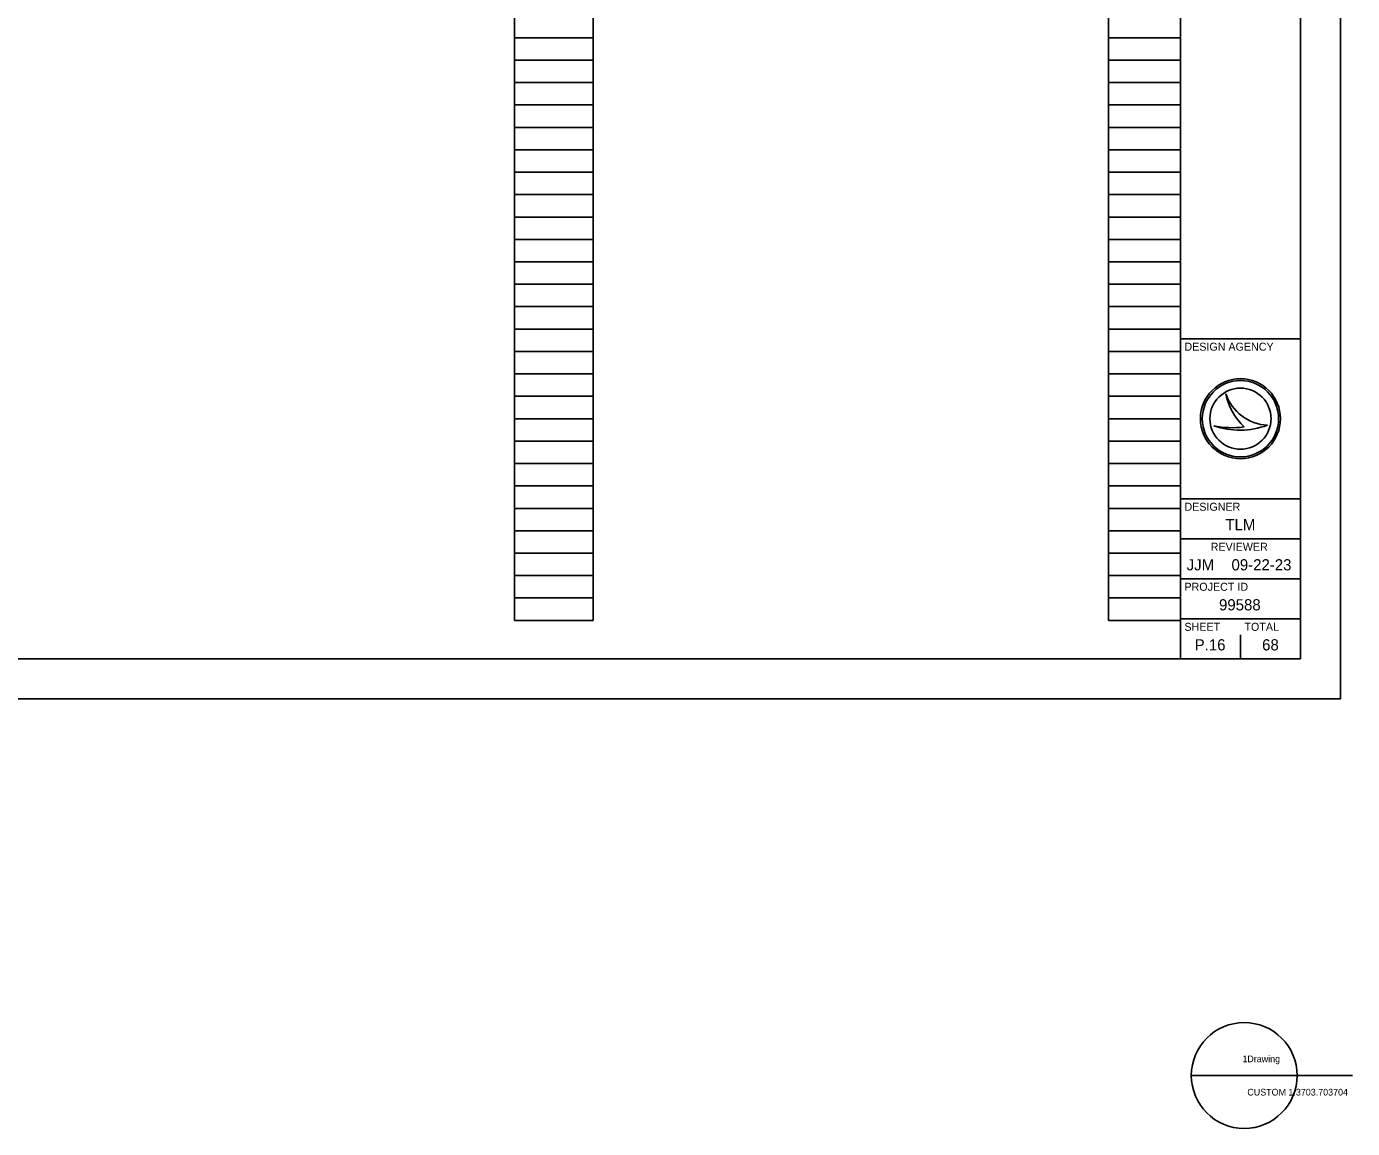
# Model space of a CAD drawing. Extents: x 0 to 34.1, y -5.4 to 22.
# Drawn here: x 17.58 to 34.15, y -5.37 to 8.4 of the extents above; entities that cross this region are included whole.
import ezdxf

# ---------------------------------------------------------------- set-up
doc = ezdxf.new("R2010")
doc.units = 0
for name, color, linetype in [('SH_Border', 7, 'Continuous'), ('SH_Cut_Line', 7, 'Continuous'), ('SH_Data', 7, 'Continuous'), ('SH_Text', 7, 'Continuous')]:
    doc.layers.add(name, color=color, linetype=linetype)

msp = doc.modelspace()

# ---------------------------------------------------------------- linework, layer by layer
at = {"layer": 'SH_Border'}
for p, q in [((32, 0.5), (32, 21.5)), ((32, 4.5), (33.5, 4.5)), ((32, 2.5), (33.5, 2.5)), ((32, 2), (33.5, 2)), ((32, 1.5), (33.5, 1.5)), ((32, 1), (33.5, 1))]:
    msp.add_line(p, q, dxfattribs=at)
msp.add_lwpolyline([(1.5, 21.5), (33.5, 21.5), (33.5, 0.5), (1.5, 0.5)], close=True, dxfattribs=at)
at = {"layer": 'SH_Cut_Line'}
msp.add_lwpolyline([(0, 0), (34, 0), (34, 22), (0, 22)], close=True, dxfattribs=at)
at = {"layer": 'SH_Data'}
for p, q in [((23.68, 0.98), (23.68, 21.14)), ((24.66, 0.98), (24.66, 21.14)), ((31.1, 0.98), (31.1, 21.14)), ((32, 0.98), (32, 21.14)), ((23.68, 8.26), (24.66, 8.26)), ((31.1, 8.26), (32, 8.26)), ((23.68, 7.98), (24.66, 7.98)), ((31.1, 7.98), (32, 7.98)), ((23.68, 7.7), (24.66, 7.7)), ((31.1, 7.7), (32, 7.7)), ((23.68, 7.42), (24.66, 7.42)), ((31.1, 7.42), (32, 7.42)), ((23.68, 7.14), (24.66, 7.14)), ((31.1, 7.14), (32, 7.14)), ((23.68, 6.86), (24.66, 6.86)), ((31.1, 6.86), (32, 6.86)), ((23.68, 6.58), (24.66, 6.58)), ((31.1, 6.58), (32, 6.58)), ((23.68, 6.3), (24.66, 6.3)), ((31.1, 6.3), (32, 6.3)), ((23.68, 6.02), (24.66, 6.02)), ((31.1, 6.02), (32, 6.02)), ((23.68, 5.74), (24.66, 5.74)), ((31.1, 5.74), (32, 5.74)), ((23.68, 5.46), (24.66, 5.46)), ((31.1, 5.46), (32, 5.46)), ((23.68, 5.18), (24.66, 5.18)), ((31.1, 5.18), (32, 5.18)), ((23.68, 4.9), (24.66, 4.9)), ((31.1, 4.9), (32, 4.9)), ((23.68, 4.62), (24.66, 4.62)), ((31.1, 4.62), (32, 4.62)), ((23.68, 4.34), (24.66, 4.34)), ((31.1, 4.34), (32, 4.34)), ((23.68, 4.06), (24.66, 4.06)), ((31.1, 4.06), (32, 4.06)), ((23.68, 3.78), (24.66, 3.78)), ((31.1, 3.78), (32, 3.78)), ((32.567, 3.81), (32.567, 3.81)), ((23.68, 3.5), (24.66, 3.5)), ((31.1, 3.5), (32, 3.5)), ((32.75, 3.5), (32.75, 3.5)), ((32.417, 3.41), (32.417, 3.41)), ((33.087, 3.419), (33.087, 3.419)), ((23.68, 3.22), (24.66, 3.22)), ((31.1, 3.22), (32, 3.22)), ((23.68, 2.94), (24.66, 2.94)), ((31.1, 2.94), (32, 2.94)), ((23.68, 2.66), (24.66, 2.66)), ((31.1, 2.66), (32, 2.66)), ((23.68, 2.38), (24.66, 2.38)), ((31.1, 2.38), (32, 2.38)), ((23.68, 2.1), (24.66, 2.1)), ((31.1, 2.1), (32, 2.1)), ((23.68, 1.82), (24.66, 1.82)), ((31.1, 1.82), (32, 1.82)), ((23.68, 1.54), (24.66, 1.54)), ((31.1, 1.54), (32, 1.54)), ((23.68, 1.26), (24.66, 1.26)), ((31.1, 1.26), (32, 1.26)), ((23.68, 0.98), (24.66, 0.98)), ((31.1, 0.98), (32, 0.98)), ((32.375, 0.675), (32.375, 0.675)), ((32.75, 0.5), (32.75, 0.8))]:
    msp.add_line(p, q, dxfattribs=at)
for radius in [0.5, 0.477, 0.477, 0.382]:
    msp.add_circle((32.75, 3.5), radius, dxfattribs=at)
for centre, radius, start, end in [((33.116, 3.998), 0.58, 198.9257, 198.9319), ((33.347, 3.97), 0.796, 191.6379, 191.6421), ((33.116, 3.998), 0.58, 198.9319, 267.1657), ((33.347, 3.97), 0.796, 191.6421, 226.0947), ((32.739, 4.37), 1.013, 251.4576, 290.0832), ((32.648, 4.654), 1.266, 259.4964, 259.4995), ((32.739, 4.37), 1.013, 251.4527, 251.4576), ((32.648, 4.654), 1.266, 259.4995, 276.6672)]:
    msp.add_arc(centre, radius, start, end, dxfattribs=at)
at = {"layer": 'SH_Text'}
for p, q in [((32.136, -4.706), (33.459, -4.706)), ((32.803, -4.706), (34.15, -4.706))]:
    msp.add_line(p, q, dxfattribs=at)
msp.add_circle((32.797, -4.706), 0.661, dxfattribs=at)

# ---------------------------------------------------------------- texts
at = {"layer": 'SH_Data'}
for s, height, p in [('DESIGN AGENCY', 0.1, (32.05, 4.35)), ('DESIGNER', 0.1, (32.05, 2.35)), ('TLM', 0.14, (32.562, 2.105)), ('REVIEWER', 0.1, (32.378, 1.85)), ('JJM', 0.14, (32.078, 1.605)), ('09-22-23', 0.14, (32.638, 1.605)), ('PROJECT ID', 0.1, (32.05, 1.35)), ('99588', 0.14, (32.482, 1.105)), ('SHEET', 0.1, (32.05, 0.85)), ('TOTAL', 0.1, (32.8, 0.85)), ('P.16', 0.14, (32.178, 0.605)), ('68', 0.14, (33.021, 0.605))]:
    msp.add_text(s, height=height, dxfattribs=at).set_placement(p)
at = {"layer": 'SH_Text'}
for s, height, p in [('1', 0.0833, (32.776, -4.54)), ('Drawing', 0.0833, (32.836, -4.54)), ('CUSTOM 1:3703.703704', 0.08333, (32.836, -4.956))]:
    msp.add_text(s, height=height, dxfattribs=at).set_placement(p)

doc.saveas('drawing.dxf')
